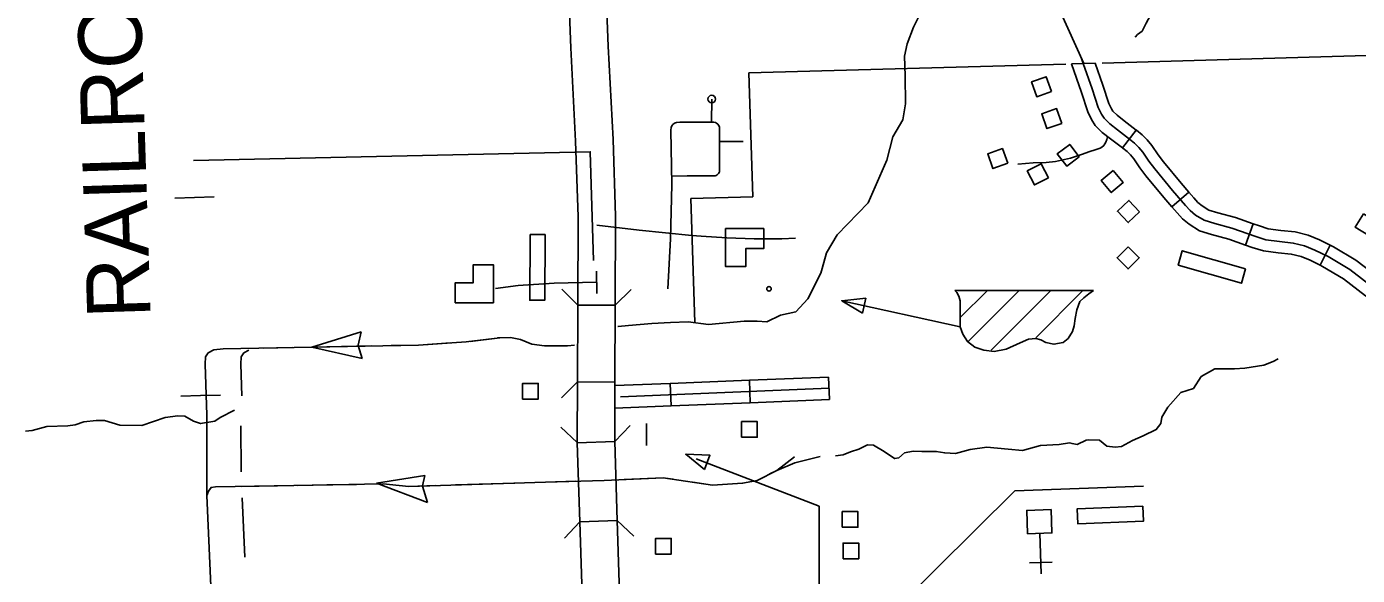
# Model space of a CAD drawing. Extents: x 155 to 3386, y 68 to 2138.
# Drawn here: x 1602.6 to 1855.9, y 949 to 1053.4 of the extents above; entities that cross this region are included whole.
import ezdxf

# ---------------------------------------------------------------- set-up
doc = ezdxf.new("R2010")
doc.units = 0
for name, color, linetype in [('Level 10', 7, 'Continuous'), ('Level 31', 7, 'Continuous'), ('Level 32', 7, 'Continuous'), ('Level 33', 7, 'Continuous'), ('Level 35', 7, 'Continuous'), ('Level 37', 7, 'Continuous'), ('Level 40', 7, 'Continuous'), ('Level 43', 7, 'Continuous'), ('Level 56', 7, 'Continuous'), ('Level 57', 7, 'Continuous'), ('Level 58', 7, 'Continuous'), ('Level 6', 7, 'Continuous')]:
    doc.layers.add(name, color=color, linetype=linetype)

msp = doc.modelspace()

# ---------------------------------------------------------------- linework, layer by layer
at = {"layer": 'Level 10'}
for p, q in [((1707.49, 1000.4), (1714.63, 1000.37)), ((1714.57, 985.76), (1707.43, 985.79)), ((1707.4, 974.21), (1714.54, 974.44)), ((1707.88, 959.17), (1715.02, 959.39))]:
    msp.add_line(p, q, dxfattribs=at)
for points in [[(1703.21, 1138.8), (1703.63, 1124.16), (1704.7, 1087.09), (1706.16, 1049.3), (1707.07, 1031.59), (1707.55, 1017.2), (1707.49, 1000.4)], [(1714.63, 1000.37), (1714.7, 1017.31), (1714.21, 1031.89), (1713.29, 1049.62), (1711.84, 1087.34), (1710.77, 1124.37), (1710.35, 1139.01)], [(1707.49, 1000.4), (1707.43, 985.79)], [(1714.63, 1000.37), (1714.57, 985.76)], [(1707.43, 985.79), (1707.39, 974.55), (1707.4, 974.21)], [(1714.54, 974.44), (1714.53, 974.65), (1714.57, 985.76)], [(1707.4, 974.21), (1707.88, 959.17)], [(1714.54, 974.44), (1715.02, 959.39)], [(1713.3, 880.88), (1710.88, 880.71), (1711.33, 884.41), (1709.98, 900.17), (1708.57, 937.42), (1707.88, 959.17)], [(1715.02, 959.39), (1715.71, 937.67), (1717.11, 900.61), (1718.45, 885.02), (1719.43, 881.31), (1717, 881.14)]]:
    msp.add_lwpolyline(points, dxfattribs=at)
at = {"layer": 'Level 31'}
msp.add_lwpolyline([(1741.06, 1012.98), (1735.85, 1013.16), (1731, 1013.49), (1729.23, 1013.66)], dxfattribs=at)
at = {"layer": 'Level 32'}
for p, q in [((1813.8, 1033.68), (1811.18, 1030.29)), ((1823.8, 1021.87), (1820.55, 1019.08)), ((1836.03, 1015.87), (1834.61, 1011.82)), ((1850.7, 1011.8), (1848.79, 1007.97)), ((1711.03, 1006.87), (1711.12, 1002.58)), ((1725.09, 985.49), (1725.26, 981.21)), ((1740.16, 986.1), (1740.34, 981.82)), ((1755.24, 986.71), (1755.41, 982.43))]:
    msp.add_line(p, q, dxfattribs=at)
for points in [[(1813.8, 1033.68), (1811.52, 1035.44), (1810.14, 1036.5), (1809.35, 1037.27), (1809.06, 1037.75), (1808.56, 1038.76), (1807.43, 1042.23), (1805.96, 1046.4), (1801.46, 1046.28)], [(1811.18, 1030.29), (1808.9, 1032.05), (1807.33, 1033.25), (1805.98, 1034.58), (1805.3, 1035.68), (1804.58, 1037.14), (1803.37, 1040.86), (1801.46, 1046.28)], [(1803.71, 1046.34), (1803.31, 1047.49)], [(1858.91, 1003.74), (1854.41, 1007.15), (1850.29, 1009.61), (1847.78, 1010.87), (1845.84, 1011.68), (1843.66, 1012.2), (1841.03, 1012.48), (1838.45, 1012.81), (1836.55, 1013.41), (1832.01, 1015), (1828.72, 1015.89), (1826.72, 1016.52), (1825.08, 1017.53), (1824.07, 1018.36), (1823.14, 1019.35), (1820.68, 1022.22), (1817.3, 1026.3), (1816.19, 1027.74), (1815.04, 1029.48), (1814.27, 1030.39), (1813.48, 1031.22), (1812.51, 1031.96), (1810.21, 1033.74), (1808.74, 1034.88), (1807.67, 1035.93), (1807.18, 1036.71), (1806.57, 1037.95), (1805.4, 1041.55), (1803.71, 1046.34)], [(1823.8, 1021.87), (1822.32, 1023.6), (1818.98, 1027.64), (1817.94, 1028.99), (1816.76, 1030.76), (1815.87, 1031.82), (1814.92, 1032.81), (1813.82, 1033.66), (1813.8, 1033.68)], [(1791.23, 1027.2), (1794.14, 1027.44), (1796.66, 1027.52), (1798.43, 1027.71), (1801.29, 1028.34), (1803.39, 1029.01), (1804.93, 1029.64), (1805.94, 1029.93), (1806.95, 1030.25), (1807.26, 1030.44), (1807.61, 1030.73), (1808.01, 1031.36), (1808.16, 1031.92), (1808.34, 1032.42)], [(1820.55, 1019.08), (1819.04, 1020.84), (1815.63, 1024.96), (1814.45, 1026.49), (1813.32, 1028.19), (1812.68, 1028.96), (1812.05, 1029.62), (1811.21, 1030.27), (1811.18, 1030.29)], [(1836.03, 1015.87), (1832.65, 1017.05), (1829.32, 1017.95), (1827.62, 1018.48), (1826.33, 1019.28), (1825.54, 1019.93), (1824.74, 1020.78), (1823.8, 1021.87)], [(1834.61, 1011.82), (1831.38, 1012.95), (1828.12, 1013.83), (1825.82, 1014.55), (1823.83, 1015.78), (1822.61, 1016.79), (1821.55, 1017.92), (1820.55, 1019.08)], [(1850.7, 1011.8), (1848.68, 1012.82), (1846.51, 1013.72), (1844.03, 1014.32), (1841.28, 1014.61), (1838.91, 1014.91), (1837.23, 1015.45), (1836.03, 1015.87)], [(1748.93, 1013.13), (1746.31, 1013.02), (1741.06, 1012.98)], [(1848.79, 1007.97), (1846.89, 1008.92), (1845.18, 1009.63), (1843.29, 1010.09), (1840.79, 1010.36), (1837.99, 1010.71), (1835.87, 1011.38), (1834.61, 1011.82)], [(1863.32, 1001.78), (1862.81, 1002.6), (1860.36, 1005.33), (1855.61, 1008.93), (1851.32, 1011.49), (1850.7, 1011.8)], [(1859.66, 999.54), (1859.36, 1000.03), (1857.45, 1002.16), (1853.21, 1005.37), (1849.26, 1007.73), (1848.79, 1007.97)], [(1711.08, 1004.73), (1703.03, 1004.56), (1696.18, 1004.15), (1691.81, 1003.57)], [(1725.09, 985.49), (1714.57, 985.07)], [(1740.16, 986.1), (1725.09, 985.49)], [(1755.24, 986.71), (1740.16, 986.1)], [(1755.32, 984.57), (1715.6, 982.96)], [(1725.26, 981.21), (1714.55, 980.78)], [(1740.34, 981.82), (1725.26, 981.21)], [(1755.41, 982.43), (1740.34, 981.82)]]:
    msp.add_lwpolyline(points, dxfattribs=at)
at = {"layer": 'Level 33'}
for points in [[(1803.82, 1046.34), (1799.27, 1056.43)], [(1732.92, 1035.18), (1732.99, 1039.59)], [(1724.65, 1003.5), (1725.17, 1012.99), (1725.39, 1023.33), (1725.21, 1033.67), (1725.27, 1034.15), (1725.42, 1034.5), (1725.62, 1034.77), (1725.93, 1035.01), (1726.31, 1035.13), (1726.92, 1035.17), (1731.87, 1035.2), (1733.41, 1035.17), (1733.68, 1035.12), (1733.87, 1035.02), (1734.15, 1034.83), (1734.31, 1034.65), (1734.41, 1034.46), (1734.45, 1034.22), (1734.47, 1033.85), (1734.48, 1025.95), (1734.44, 1025.76), (1734.38, 1025.61), (1734.28, 1025.44), (1734.16, 1025.3), (1734.03, 1025.17), (1733.85, 1025.06), (1733.62, 1024.99), (1733.37, 1024.97), (1732.9, 1024.97), (1728.34, 1024.95), (1725.36, 1024.93)], [(1734.48, 1031.54), (1739, 1031.54)], [(1729.23, 1013.66), (1719.18, 1014.67), (1711.12, 1015.61)]]:
    msp.add_lwpolyline(points, dxfattribs=at)
msp.add_circle((1732.99, 1039.59), 0.714, dxfattribs=at)
at = {"layer": 'Level 35'}
for points in [[(1827.38, 1066.58), (1825.7, 1065.57), (1823.89, 1064.16), (1822.01, 1063.42), (1821.41, 1062.68), (1821.07, 1061.54), (1820.4, 1060.74), (1819.39, 1060), (1818.39, 1058.92), (1817.65, 1057.45), (1817.31, 1056.24), (1816.44, 1055.43), (1815.7, 1054.02), (1814.9, 1052.48), (1814.03, 1051.88), (1813.57, 1051.35)], [(1773.35, 1057.2), (1771.42, 1053.24), (1770.2, 1050.08), (1769.7, 1047.74), (1769.8, 1043.98), (1769.9, 1038.69), (1769.39, 1035.64), (1767.46, 1032.39), (1766.34, 1027.96), (1762.78, 1019.82), (1756.89, 1013.78), (1754.85, 1010.32), (1754.04, 1007.37), (1753.74, 1006.46), (1751.3, 1001.57), (1748.98, 999.14), (1746.09, 998.48), (1743.49, 997.21), (1741.61, 997.31), (1739.17, 997.36), (1732.36, 996.7), (1728.53, 997.2), (1725.17, 997.1), (1721.62, 996.9), (1717.14, 996.49), (1715.17, 996.34), (1715.11, 996.33)], [(1706.85, 992.76), (1705.56, 992.62), (1703.32, 992.62), (1701.18, 992.62), (1698.75, 992.93), (1696.61, 993.84), (1694.68, 994.25), (1692.65, 994.15), (1692.21, 994.14)], [(1840.82, 990.19), (1839.82, 989.69), (1838.05, 988.98), (1835.69, 988.6), (1834.45, 988.37), (1832.51, 988.27), (1830.78, 988.27), (1828.75, 988.29), (1826.12, 986.81), (1824.66, 984.55), (1822.28, 983.77), (1819.78, 980.95), (1818.65, 979.08), (1818.48, 977.87), (1817.6, 976.7), (1815.09, 975.52), (1813.1, 974.61), (1811, 973.51), (1809.77, 973.38), (1808.16, 973.57), (1806.79, 974.67), (1804.66, 974.79), (1804.25, 974.71), (1802.57, 973.89), (1801.57, 974.05), (1801.06, 974.18), (1799.11, 973.88), (1795.54, 973.68), (1792.12, 972.75), (1789.39, 973.01), (1785.34, 973.34), (1782.16, 972.91), (1779.36, 972.16), (1777.33, 972.27), (1775.72, 972.57), (1772.97, 972.52), (1771.35, 972.61), (1769.7, 972.3), (1768.63, 971.34), (1767.8, 971.19), (1765.84, 972.52), (1763.78, 973.76), (1762.66, 973.82), (1760.98, 973), (1759.43, 972.48), (1758.03, 971.92), (1756.52, 971.75)], [(1642.14, 980.41), (1639.43, 979.02), (1638.42, 978.33), (1635.7, 977.86), (1634.38, 978.32), (1632.7, 979.24), (1631.38, 979.34), (1628.99, 979.03), (1624.52, 977.46), (1620.35, 977.56), (1617.4, 978.47), (1615.82, 978.47), (1613.49, 978.17), (1611.86, 977.61), (1610.44, 977.41), (1606.42, 977.31), (1603.68, 976.54), (1602.36, 976.44)]]:
    msp.add_lwpolyline(points, dxfattribs=at)
at = {"layer": 'Level 37'}
for points in [[(1707.49, 1000.4), (1704.47, 1003.44)], [(1717.67, 1003.39), (1714.63, 1000.37)], [(1704.39, 982.77), (1707.43, 985.79)], [(1707.4, 974.24), (1704.29, 977.19)], [(1717.49, 977.52), (1714.54, 974.42)], [(1704.95, 956.04), (1707.88, 959.17)], [(1715.02, 959.39), (1718.14, 956.46)]]:
    msp.add_lwpolyline(points, dxfattribs=at)
at = {"layer": 'Level 40'}
for p, q in [((1634.55, 1020.86), (1630.78, 1020.75)), ((1634.55, 1020.86), (1638.32, 1020.98)), ((1635.72, 983.17), (1631.95, 983.05)), ((1635.72, 983.17), (1639.49, 983.28))]:
    msp.add_line(p, q, dxfattribs=at)
at = {"layer": 'Level 43'}
for p, q in [((1666.25, 995.31), (1656.89, 992.4)), ((1665.67, 992.76), (1666.25, 995.31)), ((1656.89, 992.4), (1666.45, 990.23)), ((1666.45, 990.23), (1665.68, 992.73)), ((1669.19, 966.54), (1678.42, 968.01)), ((1678.42, 968.01), (1677.95, 966)), ((1669.19, 966.54), (1678.9, 962.83)), ((1678.9, 962.83), (1677.95, 965.97))]:
    msp.add_line(p, q, dxfattribs=at)
for points in [[(1692.65, 994.15), (1686.24, 993.4), (1677.19, 992.79), (1639.99, 992.08), (1638.24, 991.9), (1637.17, 991.29), (1636.66, 990.53), (1636.56, 989.15), (1636.87, 979.44), (1636.91, 964.17)], [(1683.27, 993.2), (1677.19, 992.79), (1671.97, 992.69)], [(1692.65, 994.15), (1687.03, 993.49)], [(1644.87, 991.8), (1643.97, 991.29), (1643.46, 990.53), (1643.36, 989.15), (1643.55, 983.12)], [(1653.12, 992.33), (1647.69, 992.22)], [(1668.2, 992.62), (1656.89, 992.4)], [(1643.39, 977.42), (1643.42, 968.66)], [(1748.72, 971.5), (1745.37, 968.95), (1741.61, 967.02), (1738.86, 966.51), (1733.17, 966.11), (1727.98, 966.92), (1723.72, 967.53), (1712.53, 967.02), (1701.35, 966.72), (1675.33, 965.9), (1670.45, 966.41), (1666.89, 966.31), (1660.9, 966.21), (1638.53, 965.8), (1637.72, 965.7), (1637.21, 964.99), (1636.91, 964.17), (1638.03, 938.34), (1638.13, 928.78), (1634.88, 927.26), (1606.52, 914.34), (1603.9, 913.35), (1602.88, 913.1), (1601.51, 912.94)], [(1753.61, 971.62), (1748.8, 970.42), (1745.37, 968.95), (1744.08, 968.29)], [(1725.68, 967.25), (1723.72, 967.53), (1716.33, 967.19)], [(1650.33, 966.02), (1643.42, 965.89)], [(1659.75, 966.19), (1654.1, 966.08)], [(1665.41, 966.28), (1660.9, 966.21), (1659.75, 966.19)], [(1680.47, 966.06), (1675.33, 965.9), (1672.85, 966.16)], [(1695.54, 966.54), (1684.24, 966.18)], [(1707.14, 966.87), (1701.35, 966.72), (1699.31, 966.65)], [(1740.63, 966.84), (1738.86, 966.51), (1733.17, 966.11), (1729.41, 966.7)], [(1643.64, 963.74), (1644.13, 952.43)]]:
    msp.add_lwpolyline(points, dxfattribs=at)
at = {"layer": 'Level 56'}
for points in [[(1797.66, 1041.02), (1794.85, 1040.03), (1793.86, 1042.84), (1796.67, 1043.83)], [(1799.61, 1034.96), (1796.8, 1033.98), (1795.81, 1036.79), (1798.62, 1037.78)], [(1802.95, 1028.6), (1800.58, 1026.8), (1798.77, 1029.17), (1801.14, 1030.97)], [(1789.32, 1027.36), (1786.51, 1026.37), (1785.52, 1029.19), (1788.32, 1030.18)], [(1797.06, 1024.59), (1794.4, 1023.26), (1793.06, 1025.93), (1795.72, 1027.26)], [(1809.38, 1026), (1811.3, 1023.73), (1809.02, 1021.8), (1807.1, 1024.07)], [(1814.43, 1018.14), (1812.28, 1016.09), (1810.22, 1018.25), (1812.38, 1020.3)], [(1857.02, 1017.75), (1859.57, 1016.21), (1858.03, 1013.66), (1855.48, 1015.19)], [(1698.41, 1013.82), (1701.27, 1013.81), (1701.22, 1001.31), (1698.36, 1001.32)], [(1812.25, 1011.5), (1814.35, 1009.39), (1812.24, 1007.28), (1810.14, 1009.39)], [(1834.58, 1007.31), (1833.8, 1004.56), (1821.77, 1007.99), (1822.56, 1010.73)], [(1697, 982.51), (1697, 985.49), (1699.98, 985.49), (1699.98, 982.51)], [(1738.68, 975.25), (1738.68, 978.22), (1741.66, 978.22), (1741.66, 975.25)], [(1731.62, 969.1), (1732.66, 971.82), (1728.06, 972.03)], [(1757.85, 958.15), (1757.85, 961.13), (1760.83, 961.13), (1760.83, 958.15)], [(1815.05, 962.14), (1815.16, 959.28), (1802.67, 958.81), (1802.56, 961.67)], [(1722.31, 953.03), (1722.31, 956), (1725.29, 956), (1725.29, 953.03)], [(1758, 952.15), (1758, 955.12), (1760.98, 955.12), (1760.98, 952.15)]]:
    msp.add_lwpolyline(points, close=True, dxfattribs=at)
for points in [[(1720.56, 977.88), (1720.56, 973.68)], [(1730.01, 971.13), (1753.42, 962.12), (1753.42, 945.16)], [(1815.19, 965.98), (1790.71, 965.05), (1760.83, 935.44)]]:
    msp.add_lwpolyline(points, dxfattribs=at)
at = {"layer": 'Level 57'}
for p, q in [((1779.28, 1003.17), (1805.68, 1003.17)), ((1780.37, 998.1), (1785.34, 1003.07)), ((1781.84, 993.51), (1791.37, 1003.04)), ((1786.19, 991.8), (1797.47, 1003.08)), ((1794.65, 994.19), (1803.48, 1003.03)), ((1795.71, 949.29), (1795.42, 956.98)), ((1797.77, 951.51), (1793.49, 951.35))]:
    msp.add_line(p, q, dxfattribs=at)
for points in [[(1779.28, 1003.17), (1779.66, 1002.76), (1780.01, 1002.12), (1780.25, 1001.18), (1780.25, 999.76), (1780.29, 997.9), (1780.29, 996.25), (1780.76, 994.87), (1781.67, 993.45), (1783.09, 992.42), (1784.75, 991.79), (1786.76, 991.59), (1789.05, 992.03), (1791.69, 993.21), (1793.3, 993.92), (1794.69, 994.04), (1795.63, 993.76), (1796.58, 993.29), (1798.12, 992.93), (1799.89, 993.25), (1800.84, 994.04), (1801.63, 995.34), (1801.98, 996.48), (1802.18, 997.82), (1802.5, 999.52), (1803.05, 1001.06), (1803.8, 1001.77), (1804.74, 1002.52), (1805.68, 1003.17)], [(1780.29, 996.25), (1757.74, 1001.22)]]:
    msp.add_lwpolyline(points, dxfattribs=at)
for points in [[(1761.7, 998.85), (1762.32, 1001.7), (1757.74, 1001.22)], [(1797.57, 961.52), (1797.74, 957.06), (1793.11, 956.89), (1792.95, 961.34)]]:
    msp.add_lwpolyline(points, close=True, dxfattribs=at)
msp.add_circle((1743.89, 1003.49), 0.429, dxfattribs=at)
at = {"layer": 'Level 58'}
for points in [[(1735.63, 1014.96), (1735.63, 1007.71), (1739.46, 1007.71), (1739.46, 1011.14), (1742.89, 1011.14), (1742.89, 1014.96)], [(1691.44, 1000.83), (1691.44, 1008.08), (1687.61, 1008.08), (1687.61, 1004.65), (1684.19, 1004.65), (1684.19, 1000.83)]]:
    msp.add_lwpolyline(points, close=True, dxfattribs=at)
at = {"layer": 'Level 6'}
for points in [[(1807.32, 1046.44), (1862.06, 1047.97), (1857.33, 1202.89), (1933.53, 1204.84), (1931.34, 1271.07)], [(1729.75, 997.11), (1729.02, 1020.67), (1740.8, 1021), (1740.06, 1044.56), (1800.38, 1046.25)], [(1634.33, 1027.91), (1709.87, 1029.57), (1710.52, 1008.89)]]:
    msp.add_lwpolyline(points, dxfattribs=at)

# ---------------------------------------------------------------- texts
at = {"layer": 'Level 40'}
msp.add_text('RAILROAD', height=12.069, rotation=91.8187, dxfattribs=at).set_placement((1626.22, 998.01))

doc.saveas('drawing.dxf')
